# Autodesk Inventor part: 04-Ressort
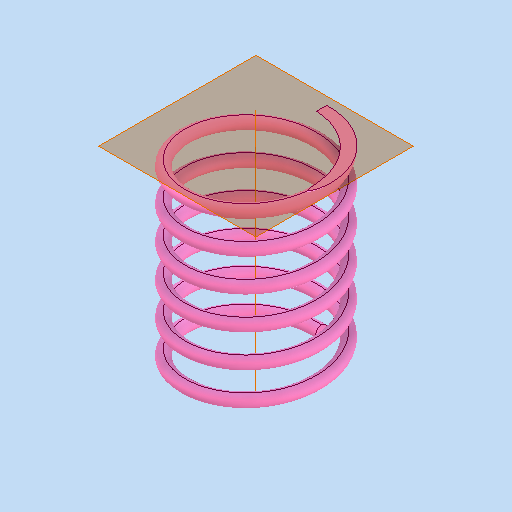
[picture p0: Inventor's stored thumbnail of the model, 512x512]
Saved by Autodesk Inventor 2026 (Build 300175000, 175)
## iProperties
Created: 2025-12
Part Number: 04-Ressort
Material: Générique
Document SubType Name: Modeling
Designer: thierry.jost
Density: 1 g/cm^3
Appearance: Rose
Author: thierry.jost
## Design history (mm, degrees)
sketch "Esquisse1"
  geometry: L1 (0, 0)-(9.567, 0); C1 r 1 at (0, -11)
  constraints: 2 end point, 1 centre point, 1 horizontal
  dimensions: "d0" = 2 diameter of C1; "d1" = 22 diameter of C1.centre L1
feature "Hélicoïde1" sketch "Esquisse1" pitch "d2" = 5.5; turns "d4" = 6; dims "d3" = 10, "d5" = 0, angle "d6" = 90 deg, angle "d7" = 90 deg, "d8" = 0, "d9" = 0
node "Plan de construction1"
sketch "Esquisse2"
  geometry: L1 (20.483, 24.136)-(-18.327, 24.136); L2 (-18.327, 24.136)-(-18.327, -22.22); L3 (-18.327, -22.22)-(20.483, -22.22); L4 (20.483, -22.22)-(20.483, 24.136); 1 further point
  constraints: 8 end point, 2 parallel, 1 horizontal, 1 perpendicular
extrude "Extrusion1" cut sketch "Esquisse2" distance "d11" = 10; taper "d12" = 0 deg
node "Solide1"
other parameters: "d10" = 32.46
